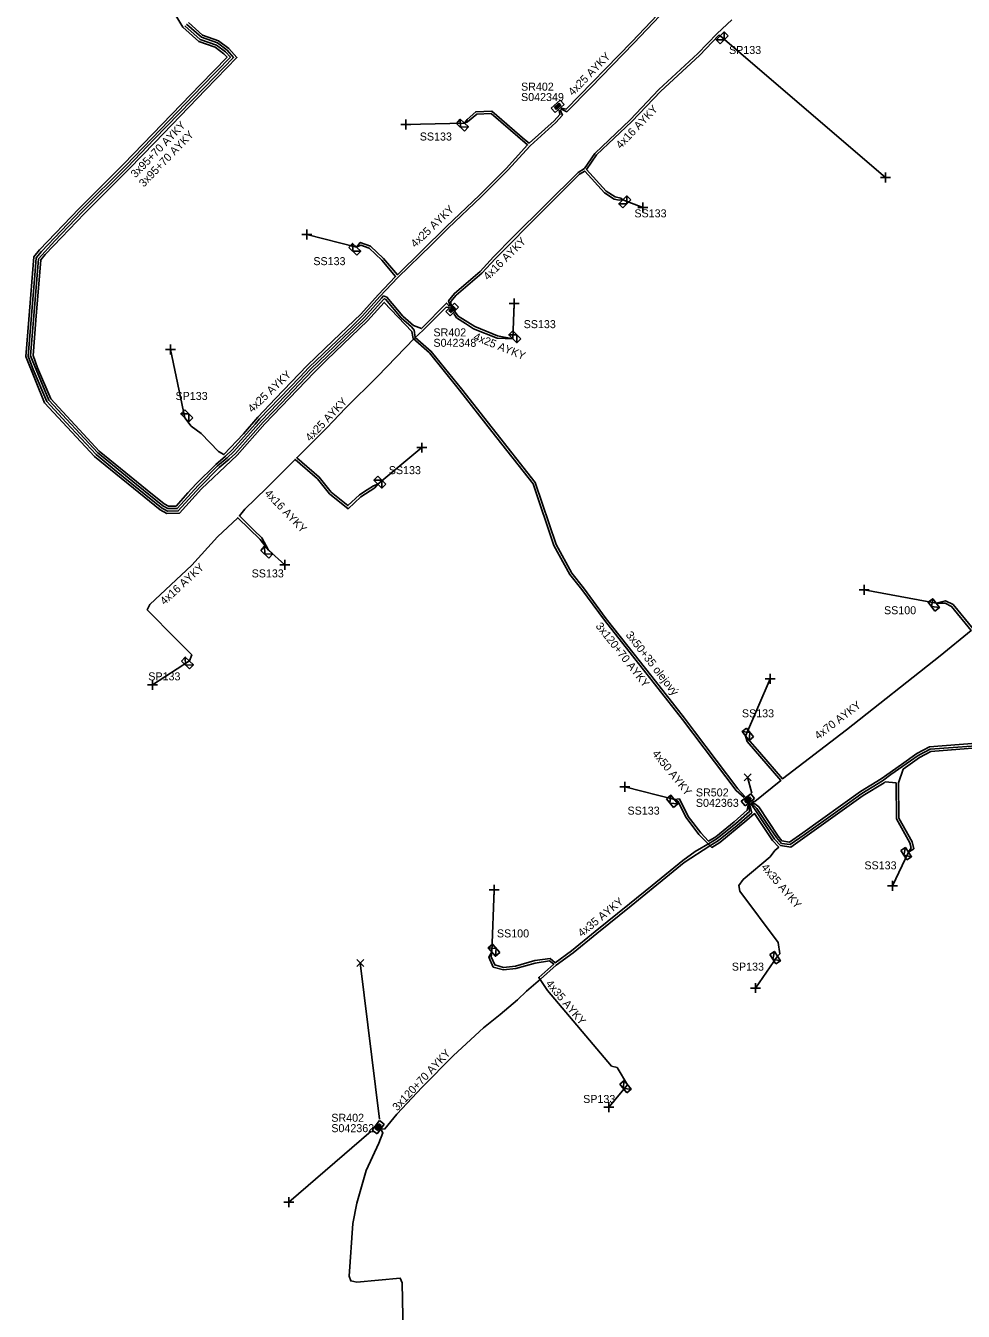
# Model space of a CAD drawing. Extents: x -748492 to -735633, y -1146251 to -1139940.
# Drawn here: x -736642.7 to -736525.5, y -1144461 to -1144300.4 of the extents above; entities that cross this region are included whole.
import ezdxf

# ---------------------------------------------------------------- set-up
doc = ezdxf.new("R2010")
doc.units = 0
for name, color, linetype in [('Vrstva 1', 7, 'Continuous'), ('Vrstva 28', 7, 'Continuous'), ('Vrstva 29', 7, 'Continuous'), ('Vrstva 30', 7, 'Continuous'), ('Vrstva 31', 7, 'Continuous'), ('Vrstva 33', 7, 'Continuous'), ('Vrstva 34', 7, 'Continuous'), ('Vrstva 5', 7, 'Continuous'), ('Vrstva 52', 7, 'Continuous'), ('Vrstva 54', 7, 'Continuous'), ('Vrstva 59', 7, 'Continuous'), ('Vrstva 6', 7, 'Continuous'), ('Vrstva 8', 7, 'Continuous'), ('Vrstva 9', 7, 'Continuous')]:
    doc.layers.add(name, color=color, linetype=linetype)

# ---------------------------------------------------------------- blocks, each defined once
blk = doc.blocks.new('NN800')
at = {"layer": 'Vrstva 1'}
for points in [[(-0.44, 0.44), (0.44, -0.44)], [(-0.44, -0.44), (0.44, 0.44)]]:
    blk.add_lwpolyline(points, dxfattribs=at)
blk = doc.blocks.new('NN620')
at = {"layer": 'Vrstva 8'}
for points in [[(0.75, 0), (-0.75, 0)], [(-0.75, 0), (-0.75, -0.75)], [(0.75, -0.75), (0.75, 0)], [(-0.75, -0.75), (0.75, -0.75)], [(0.37, -0.18), (-0.38, -0.18)], [(-0.38, -0.18), (-0.38, -0.56)], [(-0.38, -0.56), (0.37, -0.56)], [(0.32, -0.23), (-0.33, -0.23)], [(-0.33, -0.23), (-0.33, -0.51)], [(-0.33, -0.51), (0.32, -0.51)], [(0.27, -0.27), (-0.28, -0.27)], [(-0.28, -0.27), (-0.28, -0.46)], [(-0.28, -0.46), (0.27, -0.46)], [(0.23, -0.32), (-0.23, -0.32)], [(-0.23, -0.32), (-0.23, -0.42)], [(-0.23, -0.42), (0.23, -0.42)], [(-0.19, -0.37), (0.19, -0.37)], [(0.23, -0.42), (0.23, -0.32)], [(0.27, -0.46), (0.27, -0.27)], [(0.32, -0.51), (0.32, -0.23)], [(0.37, -0.56), (0.37, -0.18)]]:
    blk.add_lwpolyline(points, dxfattribs=at)
blk = doc.blocks.new('NN630')
at = {"layer": 'Vrstva 9'}
for points in [[(0, -0.7), (-0.7, 0)], [(-0.7, -0.7), (-0.7, 0), (0.7, 0), (0.7, -0.7)], [(-0.7, -0.7), (0.7, -0.7)], [(0, -0.7), (0.7, 0)]]:
    blk.add_lwpolyline(points, dxfattribs=at)

msp = doc.modelspace()

# ---------------------------------------------------------------- linework, layer by layer
at = {"layer": 'Vrstva 5'}
for points in [[(-736575.73, -1144310.73), (-736575.15, -1144310.83), (-736566.94, -1144302.42), (-736563.76, -1144299.04), (-736564.88, -1144297.81), (-736567.5, -1144295.4), (-736568.38, -1144295.76), (-736569.74, -1144297.09), (-736570.38, -1144297.25), (-736569.92, -1144296.85), (-736568.54, -1144295.5), (-736567.44, -1144295.06), (-736564.66, -1144297.59), (-736563.53, -1144298.84), (-736559.61, -1144295.08), (-736554.48, -1144289.98), (-736552.32, -1144287.4), (-736555.59, -1144283.76), (-736555.73, -1144283.31)], [(-736625.24, -1144296.89), (-736623.03, -1144300.61), (-736621.03, -1144302.4), (-736619, -1144303.1), (-736617.91, -1144303.93), (-736617.51, -1144304.36), (-736620.82, -1144307.77), (-736630.39, -1144317.67), (-736635.98, -1144323.26), (-736640.92, -1144328.43), (-736641.63, -1144329.3), (-736642.28, -1144337.12), (-736642.66, -1144341.76), (-736640.3, -1144347.53), (-736634.08, -1144354.22), (-736625.86, -1144360.91), (-736625.03, -1144361.35), (-736623.46, -1144361.32), (-736620.71, -1144358.28), (-736617, -1144354.77), (-736616.24, -1144354.05), (-736612.78, -1144350.15), (-736606.65, -1144343.73), (-736605.04, -1144342.17), (-736599.95, -1144337.3), (-736597.88, -1144334.99), (-736594.43, -1144338.63), (-736594.25, -1144339.5), (-736592.22, -1144341.3), (-736588.48, -1144345.96), (-736584.42, -1144351.11), (-736579.27, -1144357.64), (-736576.7, -1144365.35), (-736574.68, -1144368.98), (-736573.21, -1144370.84), (-736570.38, -1144374.68), (-736566.88, -1144379.12), (-736560.63, -1144387.09), (-736553.92, -1144395.96), (-736552.9, -1144396.84)], [(-736622.79, -1144300.42), (-736620.87, -1144302.14), (-736618.85, -1144302.83), (-736617.7, -1144303.7), (-736617.1, -1144304.36), (-736620.6, -1144307.98), (-736624.75, -1144312.27), (-736630.17, -1144317.89), (-736635.76, -1144323.47), (-736640.7, -1144328.62), (-736641.34, -1144329.42), (-736641.51, -1144331.6), (-736641.98, -1144337.14), (-736642.36, -1144341.72), (-736641.73, -1144343.37), (-736640.04, -1144347.37), (-736637.59, -1144350), (-736633.88, -1144354), (-736631.38, -1144356.05), (-736625.69, -1144360.66), (-736624.96, -1144361.05), (-736623.6, -1144361.03), (-736620.92, -1144358.07), (-736618.49, -1144355.62), (-736617.23, -1144354.58), (-736616.46, -1144353.84), (-736613, -1144349.95), (-736611.55, -1144348.43), (-736606.86, -1144343.52), (-736604.88, -1144341.62), (-736600.17, -1144337.09), (-736597.98, -1144334.64), (-736597.87, -1144334.52), (-736597.73, -1144334.58), (-736595.77, -1144336.91), (-736594.49, -1144338.05), (-736594.14, -1144338.44), (-736594, -1144339.36), (-736592, -1144341.1), (-736588.24, -1144345.78), (-736584.4, -1144350.66), (-736579.02, -1144357.48), (-736576.42, -1144365.23), (-736574.43, -1144368.82), (-736572.97, -1144370.66), (-736570.14, -1144374.5), (-736566.64, -1144378.94), (-736564.01, -1144382.31), (-736560.39, -1144386.91), (-736559.13, -1144388.58), (-736553.7, -1144395.76), (-736552.81, -1144396.76)], [(-736589.74, -1144335.51), (-736590.11, -1144335.07), (-736593.22, -1144338.26), (-736594.21, -1144337.89), (-736595.55, -1144336.7), (-736597.55, -1144334.32), (-736597.96, -1144334.18), (-736598.2, -1144334.44), (-736600.39, -1144336.88), (-736602.04, -1144338.51), (-736607.07, -1144343.31), (-736609.23, -1144345.56), (-736613.22, -1144349.75), (-736616.68, -1144353.63), (-736617.5, -1144354.42), (-736618.71, -1144355.42), (-736621.14, -1144357.86), (-736623.73, -1144360.73), (-736624.89, -1144360.75), (-736625.52, -1144360.41), (-736628.82, -1144357.72), (-736633.67, -1144353.78), (-736639.79, -1144347.2), (-736642.05, -1144341.67), (-736641.68, -1144337.17), (-736641.05, -1144329.53), (-736639.03, -1144327.3), (-736635.55, -1144323.68), (-736629.96, -1144318.09), (-736626.62, -1144314.61), (-736620.39, -1144308.19), (-736616.69, -1144304.37), (-736617.5, -1144303.48), (-736618.71, -1144302.56), (-736620.72, -1144301.87), (-736622.56, -1144300.23)], [(-736575.92, -1144310.91), (-736575.62, -1144311.61), (-736576.45, -1144312.52), (-736579.66, -1144315.42), (-736582.43, -1144318.47), (-736585.77, -1144321.79), (-736589.88, -1144325.73), (-736591.98, -1144327.78), (-736596.16, -1144331.86), (-736598.43, -1144334.24), (-736600.6, -1144336.67), (-736601.76, -1144337.81), (-736603.73, -1144339.69), (-736607.28, -1144343.1), (-736608.43, -1144344.31), (-736613.44, -1144349.54), (-736614, -1144350.18), (-736616.89, -1144353.42), (-736617.71, -1144354.21), (-736618.93, -1144355.22), (-736621.36, -1144357.66), (-736622.39, -1144358.79), (-736623.87, -1144360.43), (-736624.81, -1144360.45), (-736625.36, -1144360.16), (-736627.47, -1144358.42), (-736633.47, -1144353.56), (-736639.53, -1144347.04), (-736641.17, -1144343.14), (-736641.75, -1144341.63), (-736641.38, -1144337.19), (-736640.76, -1144329.65), (-736640.25, -1144329.02), (-736638.19, -1144326.86), (-736635.33, -1144323.89), (-736629.74, -1144318.3), (-736626.55, -1144315.02), (-736620.17, -1144308.4), (-736616.27, -1144304.37), (-736617.3, -1144303.26), (-736618.57, -1144302.3), (-736620.56, -1144301.61), (-736622.32, -1144300.03)], [(-736589.65, -1144335.42), (-736589.84, -1144334.78), (-736589.11, -1144333.86), (-736585.88, -1144331.11), (-736584.22, -1144329.28), (-736581.76, -1144326.8), (-736573.67, -1144318.74), (-736572.88, -1144318.25), (-736571.59, -1144316.37), (-736567.16, -1144312.16), (-736563.56, -1144308.37), (-736558.7, -1144303.9), (-736556.31, -1144301.41), (-736554.45, -1144299.7)], [(-736575.83, -1144310.82), (-736575.05, -1144311.17), (-736572.08, -1144308.12), (-736566.72, -1144302.62), (-736563.44, -1144299.17)], [(-736601.33, -1144328.09), (-736600.87, -1144327.49), (-736599.58, -1144327.96), (-736597.95, -1144329.52), (-736596.24, -1144331.53), (-736590.08, -1144325.51), (-736585.97, -1144321.57), (-736582.65, -1144318.27), (-736579.98, -1144315.31), (-736584.53, -1144311.4), (-736586.32, -1144311.47), (-736587.46, -1144312.42), (-736587.87, -1144312.59), (-736587.53, -1144312.13), (-736586.44, -1144311.17), (-736584.43, -1144311.1), (-736580.34, -1144314.62), (-736579.77, -1144315.09), (-736576.67, -1144312.3), (-736575.94, -1144311.53), (-736576.02, -1144311)], [(-736568.08, -1144322.18), (-736568.55, -1144322.2), (-736569.14, -1144322.08), (-736570.36, -1144321.31), (-736572.83, -1144318.57), (-736573.49, -1144318.98), (-736574.64, -1144320.12), (-736576.23, -1144321.71), (-736578.07, -1144323.56), (-736584, -1144329.48), (-736585.67, -1144331.33), (-736588.89, -1144334.08), (-736589.58, -1144334.87), (-736589.53, -1144335.51), (-736588.65, -1144336.69), (-736586.58, -1144338.01), (-736583.71, -1144339.16), (-736581.82, -1144339.54)], [(-736598.67, -1144357.68), (-736599.2, -1144357.89), (-736600, -1144358.4), (-736600.98, -1144359.02), (-736602.41, -1144360.37), (-736604.49, -1144358.69), (-736606, -1144356.81), (-736608.81, -1144354.38), (-736605.07, -1144350.68), (-736602.67, -1144348.15), (-736598.73, -1144344.24), (-736594.1, -1144339.47), (-736593, -1144338.47), (-736590.14, -1144335.56), (-736589.83, -1144335.6)], [(-736589.18, -1144336.38), (-736588.85, -1144336.91), (-736587.73, -1144337.61), (-736586.72, -1144338.27), (-736583.79, -1144339.46), (-736581.82, -1144339.54)], [(-736612.32, -1144365.93), (-736613.15, -1144364.4), (-736614.15, -1144363.42), (-736615.96, -1144361.66), (-736615.31, -1144360.81), (-736612.59, -1144358.21), (-736609.01, -1144354.6), (-736606.22, -1144357.01), (-736604.71, -1144358.91), (-736602.39, -1144360.77), (-736600.8, -1144359.26), (-736599.04, -1144358.13), (-736598.67, -1144357.68)], [(-736551.83, -1144397.28), (-736551.6, -1144397.32), (-736548.35, -1144394.71), (-736552.53, -1144389.84), (-736552.74, -1144389.15), (-736550.99, -1144391.16), (-736548.12, -1144394.51), (-736540.14, -1144388.39), (-736528.43, -1144379.15), (-736524.57, -1144375.98), (-736527.01, -1144372.97), (-736527.83, -1144372.57), (-736528.95, -1144372.56), (-736527.79, -1144372.27), (-736526.82, -1144372.73), (-736524.33, -1144375.78)], [(-736513.19, -1144375.63), (-736514.02, -1144375.78), (-736514.97, -1144376.79), (-736515.21, -1144378.1), (-736515.44, -1144379.11), (-736517.28, -1144381.47), (-736517.9, -1144382.45), (-736518.19, -1144383.45), (-736519.23, -1144386.21), (-736519.68, -1144387.88), (-736521.2, -1144389.86), (-736523.95, -1144390.03), (-736529.77, -1144390.49), (-736531.34, -1144391.33), (-736533.26, -1144392.69), (-736535.8, -1144394.49), (-736538.4, -1144396.09), (-736545.61, -1144401.24), (-736547.24, -1144402.4), (-736548.21, -1144402.26), (-736548.67, -1144401.65), (-736551.08, -1144398), (-736551.94, -1144397.36)], [(-736552.14, -1144397.52), (-736551.56, -1144398.37), (-736549.14, -1144402.02), (-736548.38, -1144402.81), (-736547.09, -1144403.03), (-736538.07, -1144396.59), (-736535.45, -1144394.98), (-736535.3, -1144394.86), (-736533.95, -1144395.02), (-736533.89, -1144399.48), (-736532.21, -1144402.48), (-736532.07, -1144403.14), (-736532.39, -1144403.66), (-736531.73, -1144403.24), (-736531.93, -1144402.38), (-736533.59, -1144399.4), (-736533.65, -1144395.02), (-736533.07, -1144393.3), (-736531.02, -1144391.84), (-736529.6, -1144391.08), (-736523.91, -1144390.63)], [(-736598.19, -1144438.26), (-736597.79, -1144438.23), (-736596.32, -1144436.38), (-736593.16, -1144433), (-736589.23, -1144429.05), (-736585.47, -1144425.62), (-736583.41, -1144423.93), (-736581.23, -1144422.12), (-736580.11, -1144421.03), (-736578.37, -1144419.52), (-736576.4, -1144417.79), (-736574.29, -1144416.23), (-736571.33, -1144413.84), (-736567.05, -1144410.35), (-736560.41, -1144404.96), (-736557.2, -1144402.87), (-736556.12, -1144402.22), (-736553.79, -1144400.32), (-736551.98, -1144398.74), (-736552.24, -1144397.6)], [(-736584.44, -1144416.13), (-736584.51, -1144416.74), (-736584.05, -1144417.75), (-736582.97, -1144418.06), (-736581.5, -1144417.89), (-736579.07, -1144417.21), (-736577.16, -1144416.93), (-736576.51, -1144417.48), (-736574.47, -1144415.99), (-736571.51, -1144413.58), (-736567.23, -1144410.11), (-736564.4, -1144407.83), (-736560.59, -1144404.72), (-736559.05, -1144403.56), (-736557.16, -1144402.48), (-736556.29, -1144401.97), (-736553.98, -1144400.09), (-736552.26, -1144398.59), (-736552.34, -1144397.68)], [(-736561.64, -1144397.09), (-736561.01, -1144397), (-736559.92, -1144399.19), (-736558.33, -1144401.24), (-736557.39, -1144402.27), (-736556.47, -1144401.73), (-736554.18, -1144399.86), (-736552.54, -1144398.43), (-736552.44, -1144397.77)], [(-736595.43, -1144467.91), (-736595.62, -1144457.47), (-736595.88, -1144456.88), (-736601.32, -1144457.36), (-736602.06, -1144457.22), (-736602.25, -1144456.63), (-736601.78, -1144450.05), (-736601.32, -1144447.49), (-736600.13, -1144443.42), (-736598.57, -1144440), (-736598.05, -1144438.72), (-736598.27, -1144438.36)]]:
    msp.add_lwpolyline(points, dxfattribs=at)
at = {"layer": 'Vrstva 52'}
for points in [[(-736568.08, -1144322.18), (-736568.34, -1144321.97), (-736569.02, -1144321.8), (-736570.16, -1144321.07), (-736572.61, -1144318.37), (-736571.36, -1144316.57), (-736566.94, -1144312.38), (-736563.34, -1144308.59), (-736558.48, -1144304.12), (-736556.09, -1144301.61), (-736555.92, -1144301.69)], [(-736601.33, -1144328.09), (-736600.81, -1144327.83), (-736599.74, -1144328.22), (-736598.17, -1144329.72), (-736596.46, -1144331.73), (-736598.65, -1144334.04), (-736600.82, -1144336.47), (-736604.26, -1144339.74), (-736607.5, -1144342.88), (-736611.45, -1144347), (-736613.66, -1144349.34), (-736615.47, -1144351.4), (-736617.91, -1144353.99), (-736618.6, -1144353.59), (-736620.73, -1144351.38), (-736621.98, -1144350.44), (-736622.79, -1144349.41)], [(-736612.32, -1144365.93), (-736613.39, -1144364.6), (-736616.18, -1144361.88), (-736618.71, -1144364.29), (-736621.93, -1144367.81), (-736627.16, -1144372.71), (-736627.47, -1144373.38), (-736623.88, -1144377.04), (-736621.93, -1144379.02), (-736622.22, -1144379.78)], [(-736552.04, -1144397.44), (-736551.32, -1144398.19), (-736550.07, -1144400.08), (-736548.9, -1144401.84), (-736548.25, -1144402.56), (-736547.17, -1144402.71), (-736545.44, -1144401.49), (-736541.24, -1144398.5), (-736538.23, -1144396.34), (-736535.62, -1144394.73), (-736534.61, -1144393.97), (-736531.18, -1144391.58), (-736529.68, -1144390.78), (-736521.65, -1144390.2), (-736513.63, -1144389.64), (-736511.36, -1144389.69), (-736510.14, -1144390.3), (-736509.78, -1144390.68), (-736509.4, -1144396.65), (-736509.45, -1144399.3), (-736509.74, -1144399.56)], [(-736561.64, -1144397.09), (-736561.21, -1144397.28), (-736560.18, -1144399.35), (-736558.57, -1144401.44), (-736556.97, -1144403.07), (-736555.95, -1144402.47), (-736552.59, -1144399.68), (-736551.62, -1144398.84), (-736549.37, -1144402.21), (-736548.59, -1144403.02), (-736549.07, -1144403.46), (-736549.67, -1144404.23), (-736553.03, -1144407.08), (-736553.58, -1144407.84), (-736553.44, -1144408.55), (-736548.69, -1144414.94), (-736548.47, -1144416.38), (-736548.76, -1144416.65)], [(-736584.44, -1144416.13), (-736584.83, -1144416.76), (-736584.27, -1144418.01), (-736582.99, -1144418.36), (-736581.44, -1144418.19), (-736579.01, -1144417.51), (-736577.24, -1144417.25), (-736576.71, -1144417.67), (-736578.57, -1144419.3), (-736577.47, -1144420.95), (-736569.49, -1144430.41), (-736568.79, -1144430.56), (-736567.48, -1144432.74)]]:
    msp.add_lwpolyline(points, dxfattribs=at)
at = {"layer": 'Vrstva 59'}
for points in [[(-736555.92, -1144301.69), (-736535.25, -1144319.38)], [(-736587.87, -1144312.59), (-736595.19, -1144312.75)], [(-736568.08, -1144322.18), (-736565.56, -1144323.13)], [(-736601.33, -1144328.09), (-736607.56, -1144326.5)], [(-736581.82, -1144339.54), (-736581.63, -1144335.13)], [(-736622.79, -1144349.41), (-736624.56, -1144340.88)], [(-736598.67, -1144357.68), (-736593.19, -1144353.13)], [(-736612.32, -1144365.93), (-736610.31, -1144367.75)], [(-736528.95, -1144372.56), (-736537.94, -1144370.88)], [(-736622.22, -1144379.78), (-736626.81, -1144382.75)], [(-736552.74, -1144389.15), (-736549.69, -1144382)], [(-736551.98, -1144396.31), (-736552.49, -1144394.3)], [(-736561.64, -1144397.09), (-736567.81, -1144395.5)], [(-736532.39, -1144403.66), (-736534.38, -1144407.88)], [(-736584.44, -1144416.13), (-736584.13, -1144408.38)], [(-736598.48, -1144437.02), (-736600.88, -1144417.5)], [(-736548.76, -1144416.65), (-736551.5, -1144420.63)], [(-736567.48, -1144432.74), (-736569.81, -1144435.5)], [(-736599.5, -1144438.5), (-736609.8, -1144447.4)]]:
    msp.add_lwpolyline(points, dxfattribs=at)

# ---------------------------------------------------------------- block references
at = {"layer": 'Vrstva 28'}
for p, rotation in [((-736575.96, -1144310.77), -137.27408898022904), ((-736589.65, -1144335.6), 45.20804446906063), ((-736552.22, -1144397.42), -141.34019170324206), ((-736598.33, -1144438.23), -127.0025277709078)]:
    msp.add_blockref('NN620', p, dxfattribs=dict(at, rotation=rotation))
at = {"layer": 'Vrstva 31'}
for p, rotation in [((-736555.92, -1144301.69), 45.25521390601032), ((-736587.87, -1144312.59), -42.927716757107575), ((-736568.08, -1144322.18), 44.950733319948), ((-736601.33, -1144328.09), -43.298086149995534), ((-736581.82, -1144339.54), 135.66241953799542), ((-736622.79, -1144349.41), 135.52697784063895), ((-736598.67, -1144357.68), 134.48019433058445), ((-736612.32, -1144365.93), -43.36605845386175), ((-736528.95, -1144372.56), -52.7706167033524), ((-736622.22, -1144379.78), -43.52371662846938), ((-736552.74, -1144389.15), 128.65980829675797), ((-736561.64, -1144397.09), -51.28521665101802), ((-736532.39, -1144403.66), -56.168211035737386), ((-736584.44, -1144416.13), 130.45896385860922), ((-736548.76, -1144416.65), -57.2818444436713), ((-736567.48, -1144432.74), -50.60112777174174)]:
    msp.add_blockref('NN630', p, dxfattribs=dict(at, rotation=rotation))
at = {"layer": 'Vrstva 34'}
for p, rotation in [((-736595.19, -1144312.75), 44.99999995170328), ((-736535.25, -1144319.38), 45), ((-736565.56, -1144323.13), 45), ((-736607.56, -1144326.5), 45), ((-736581.63, -1144335.13), 45), ((-736624.56, -1144340.88), 45), ((-736593.19, -1144353.13), 44.99999995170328), ((-736610.31, -1144367.75), 45), ((-736537.94, -1144370.88), 44.99999995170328), ((-736626.81, -1144382.75), 45), ((-736549.69, -1144382), 44.99999995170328), ((-736567.81, -1144395.5), 45), ((-736584.13, -1144408.38), 45), ((-736534.38, -1144407.88), 45), ((-736551.5, -1144420.63), 45), ((-736569.81, -1144435.5), 45), ((-736609.8, -1144447.4), 45)]:
    msp.add_blockref('NN800', p, dxfattribs=dict(at, rotation=rotation))
for p in [(-736552.49, -1144394.3), (-736600.88, -1144417.5)]:
    msp.add_blockref('NN800', p, dxfattribs=at)

# ---------------------------------------------------------------- texts
at = {"layer": 'Vrstva 29'}
for s, p in [('S042349', (-736580.79, -1144309.83)), ('S042348', (-736591.73, -1144340.53)), ('S042363', (-736558.95, -1144398)), ('S042362', (-736604.49, -1144438.64))]:
    msp.add_text(s, height=1, dxfattribs=at).set_placement(p)
at = {"layer": 'Vrstva 30'}
for s, p in [('SR402', (-736580.79, -1144308.53)), ('SR402', (-736591.73, -1144339.23)), ('SR502', (-736558.95, -1144396.7)), ('SR402', (-736604.49, -1144437.34))]:
    msp.add_text(s, height=1, dxfattribs=at).set_placement(p)
at = {"layer": 'Vrstva 33'}
for s, p in [('SP133', (-736554.81, -1144303.95)), ('SS133', (-736593.44, -1144314.76)), ('SS133', (-736566.63, -1144324.36)), ('SS133', (-736606.73, -1144330.33)), ('SS133', (-736580.46, -1144338.2)), ('SP133', (-736623.95, -1144347.17)), ('SS133', (-736597.31, -1144356.44)), ('SS133', (-736614.44, -1144369.34)), ('SS100', (-736535.45, -1144373.94)), ('SP133', (-736627.35, -1144382.2)), ('SS133', (-736553.2, -1144386.82)), ('SS133', (-736567.49, -1144398.97)), ('SS133', (-736537.9, -1144405.81)), ('SS100', (-736583.8, -1144414.31)), ('SP133', (-736554.46, -1144418.46)), ('SP133', (-736573.03, -1144434.99))]:
    msp.add_text(s, height=1, dxfattribs=at).set_placement(p)
at = {"layer": 'Vrstva 54'}
for s, rotation, p in [('4x16 AYKY', 46.473, (-736568.34, -1144315.87)), ('4x25 AYKY', 43.567, (-736614.36, -1144348.82)), ('4x16 AYKY', 42.709, (-736625.32, -1144372.85)), ('4x35 AYKY', 310.305, (-736550.85, -1144405.59)), ('4x35 AYKY', 310.149, (-736577.77, -1144420.12))]:
    msp.add_text(s, height=1, rotation=rotation, dxfattribs=at).set_placement(p)
at = {"layer": 'Vrstva 6'}
for s, rotation, p in [('4x25 AYKY', 45.717, (-736574.31, -1144309.24)), ('3x95+70 AYKY', 46, (-736628.94, -1144319.49)), ('3x95+70 AYKY', 45.997, (-736627.91, -1144320.65)), ('4x25 AYKY', 43.79, (-736594.01, -1144328.2)), ('4x16 AYKY', 44.976, (-736584.92, -1144332.28)), ('4x25 AYKY', 338.02, (-736586.82, -1144339.63)), ('4x25 AYKY', 46.51, (-736607.12, -1144352.42)), ('4x16 AYKY', 313.708, (-736612.89, -1144358.92)), ('3x120+70 AYKY', 308.244, (-736571.53, -1144375.44)), ('3x50+35 olejový', 307.965, (-736567.77, -1144376.54)), ('4x70 AYKY', 37.486, (-736543.66, -1144389.64)), ('4x50 AYKY', 309.127, (-736564.47, -1144391.39)), ('4x35 AYKY', 39.07, (-736573.21, -1144414.31)), ('3x120+70 AYKY', 46.927, (-736596.24, -1144436.05))]:
    msp.add_text(s, height=1, rotation=rotation, dxfattribs=at).set_placement(p)

doc.saveas('drawing.dxf')
